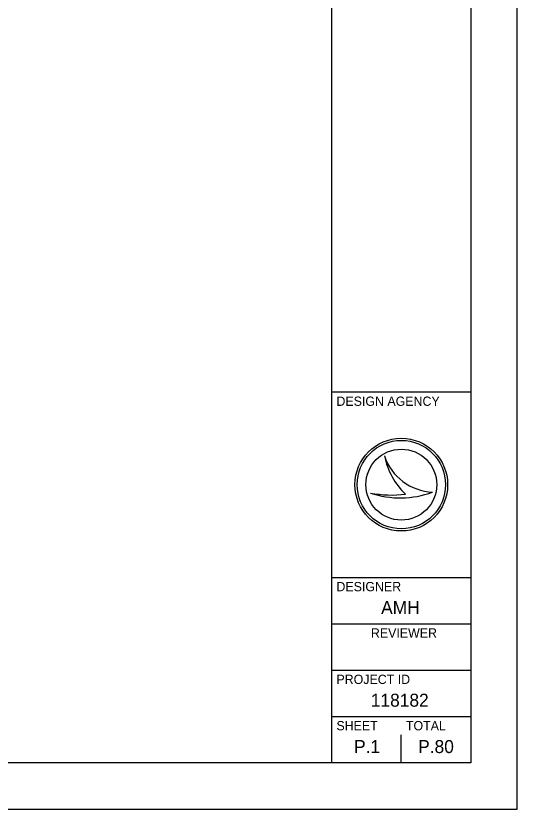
# Model space of a CAD drawing. Extents: x 0 to 34, y 0 to 22.
# Drawn here: x 28.59 to 34, y 0 to 8.56 of the extents above; entities that cross this region are included whole.
import ezdxf

# ---------------------------------------------------------------- set-up
doc = ezdxf.new("R2010")
doc.units = 0
for name, color, linetype in [('SH_Border', 7, 'Continuous'), ('SH_Cut_Line', 7, 'Continuous'), ('SH_Data', 7, 'Continuous')]:
    doc.layers.add(name, color=color, linetype=linetype)

msp = doc.modelspace()

# ---------------------------------------------------------------- linework, layer by layer
at = {"layer": 'SH_Border'}
for p, q in [((32, 0.5), (32, 21.5)), ((32, 4.5), (33.5, 4.5)), ((32, 2.5), (33.5, 2.5)), ((32, 2), (33.5, 2)), ((32, 1.5), (33.5, 1.5)), ((32, 1), (33.5, 1))]:
    msp.add_line(p, q, dxfattribs=at)
msp.add_lwpolyline([(1.5, 21.5), (33.5, 21.5), (33.5, 0.5), (1.5, 0.5)], close=True, dxfattribs=at)
at = {"layer": 'SH_Cut_Line'}
msp.add_lwpolyline([(0, 0), (34, 0), (34, 22), (0, 22)], close=True, dxfattribs=at)
at = {"layer": 'SH_Data'}
for p, q in [((32.5674, 3.8096), (32.5675, 3.8096)), ((32.75, 3.5), (32.75, 3.5)), ((32.4172, 3.4095), (32.4172, 3.4095)), ((33.0873, 3.4185), (33.0873, 3.4185)), ((32.75, 0.5), (32.75, 0.8)), ((32.375, 0.675), (32.375, 0.675))]:
    msp.add_line(p, q, dxfattribs=at)
for radius in [0.5, 0.4768, 0.4768, 0.3822]:
    msp.add_circle((32.75, 3.5), radius, dxfattribs=at)
for centre, radius, start, end in [((33.1159, 3.9976), 0.5798, 198.92567, 198.93195), ((33.3467, 3.9701), 0.7956, 191.63793, 191.64215), ((33.1159, 3.9976), 0.5798, 198.93195, 267.16574), ((33.3467, 3.9701), 0.7956, 191.64215, 226.09467), ((32.7394, 4.37), 1.0131, 251.45764, 290.08324), ((32.648, 4.6543), 1.2661, 259.49639, 259.49952), ((32.7394, 4.37), 1.0131, 251.45274, 251.45764), ((32.648, 4.6543), 1.2661, 259.49952, 276.66723)]:
    msp.add_arc(centre, radius, start, end, dxfattribs=at)

# ---------------------------------------------------------------- texts
for s, height, p in [('DESIGN AGENCY', 0.1, (32.05, 4.35)), ('DESIGNER', 0.1, (32.05, 2.35)), ('AMH', 0.14, (32.5324, 2.105)), ('REVIEWER', 0.1, (32.4218, 1.85)), ('PROJECT ID', 0.1, (32.05, 1.35)), ('118182', 0.14, (32.4209, 1.105)), ('SHEET', 0.1, (32.05, 0.85)), ('TOTAL', 0.1, (32.8, 0.85)), ('P.1', 0.14, (32.2403, 0.605)), ('P.80', 0.14, (32.9322, 0.605))]:
    msp.add_text(s, height=height, dxfattribs=at).set_placement(p)

doc.saveas('drawing.dxf')
